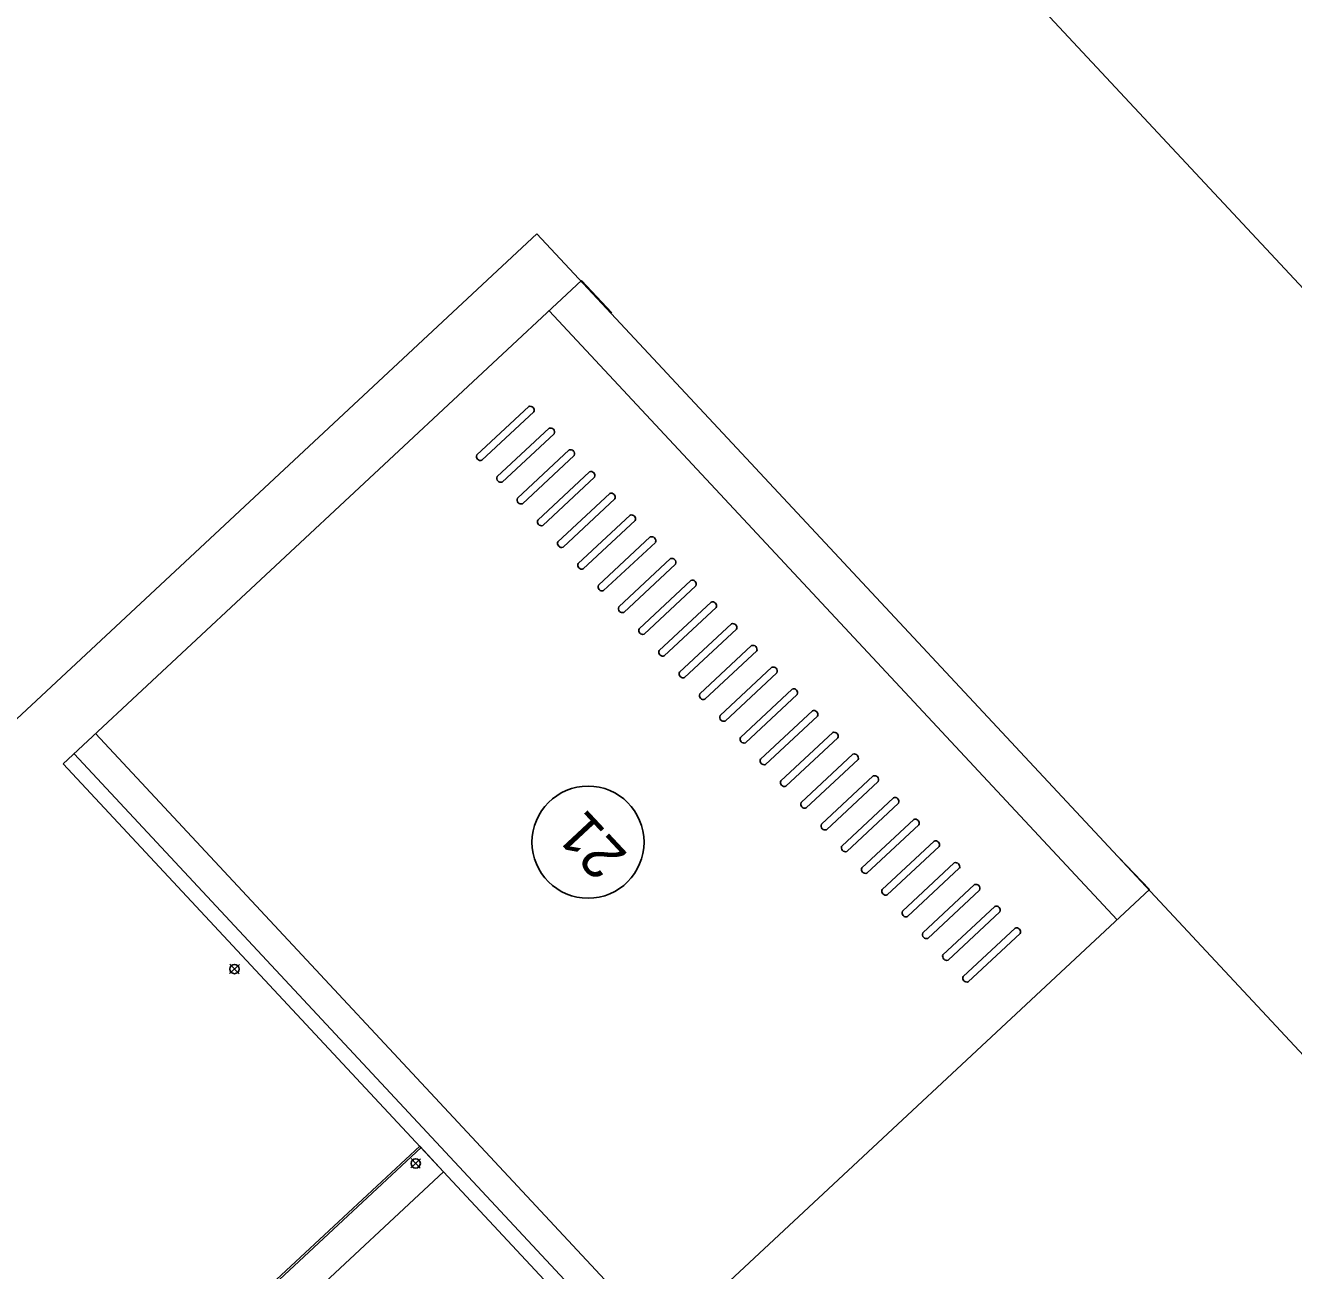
# Model space of a CAD drawing. Extents: x 1121979 to 1130574, y 1838676 to 1848573.
# Drawn here: x 1129637.05 to 1129644.21, y 1839365.55 to 1839372.58 of the extents above; entities that cross this region are included whole.
import ezdxf

# ---------------------------------------------------------------- set-up
doc = ezdxf.new("R2010")
doc.units = 0
for name, color, linetype in [('CENTER1', 7, 'Continuous'), ('IPDC BUILDING RELATED', 7, 'Continuous'), ('IPDC-PROP ELECT EQUIP', 7, 'Continuous'), ('Level 4', 7, 'Continuous'), ('PHANTOM1', 7, 'Continuous')]:
    doc.layers.add(name, color=color, linetype=linetype)

msp = doc.modelspace()

# ---------------------------------------------------------------- linework, layer by layer
at = {"layer": 'CENTER1'}
for points in [[(1129638.2621, 1839367.2816), (1129638.2072, 1839367.2305)], [(1129638.2602, 1839367.2286), (1129638.2091, 1839367.2835)]]:
    msp.add_lwpolyline(points, dxfattribs=at)
at = {"layer": 'IPDC BUILDING RELATED'}
for p, q in [((1129642.1001, 1839373.419), (1129661.457, 1839352.6561)), ((1129639.9419, 1839371.4066), (1129633.3595, 1839365.269)), ((1129639.9419, 1839371.4066), (1129659.302, 1839350.6467))]:
    msp.add_line(p, q, dxfattribs=at)
at = {"layer": 'IPDC-PROP ELECT EQUIP'}
for p, q in [((1129637.2682, 1839368.4147), (1129640.1937, 1839371.1426)), ((1129640.1937, 1839371.1426), (1129640.3642, 1839370.9597)), ((1129643.2161, 1839367.5346), (1129640.0109, 1839370.9721)), ((1129639.8953, 1839370.4311), (1129639.6028, 1839370.1583)), ((1129639.9238, 1839370.4006), (1129639.6312, 1839370.1278)), ((1129640.0097, 1839370.3084), (1129639.7171, 1839370.0356)), ((1129640.0381, 1839370.2779), (1129639.7456, 1839370.0051)), ((1129640.1241, 1839370.1858), (1129639.8315, 1839369.913)), ((1129640.1525, 1839370.1553), (1129639.8599, 1839369.8825)), ((1129640.2384, 1839370.0631), (1129639.9459, 1839369.7903)), ((1129640.2669, 1839370.0326), (1129639.9743, 1839369.7598)), ((1129640.3528, 1839369.9405), (1129640.0602, 1839369.6677)), ((1129640.3812, 1839369.91), (1129640.0887, 1839369.6372)), ((1129640.4672, 1839369.8178), (1129640.1746, 1839369.545)), ((1129640.4956, 1839369.7873), (1129640.203, 1839369.5145)), ((1129640.5815, 1839369.6951), (1129640.289, 1839369.4224)), ((1129640.61, 1839369.6646), (1129640.3174, 1839369.3919)), ((1129640.6959, 1839369.5725), (1129640.4033, 1839369.2997)), ((1129640.7243, 1839369.542), (1129640.4318, 1839369.2692)), ((1129640.8103, 1839369.4498), (1129640.5177, 1839369.1771)), ((1129640.8387, 1839369.4193), (1129640.5461, 1839369.1466)), ((1129640.9246, 1839369.3272), (1129640.6321, 1839369.0544)), ((1129640.9531, 1839369.2967), (1129640.6605, 1839369.0239)), ((1129641.039, 1839369.2045), (1129640.7464, 1839368.9317)), ((1129641.0674, 1839369.174), (1129640.7749, 1839368.9013)), ((1129641.1534, 1839369.0819), (1129640.8608, 1839368.8091)), ((1129641.1818, 1839369.0514), (1129640.8892, 1839368.7786)), ((1129641.2677, 1839368.9592), (1129640.9752, 1839368.6864)), ((1129641.2962, 1839368.9287), (1129641.0036, 1839368.6559)), ((1129641.3821, 1839368.8366), (1129641.0895, 1839368.5638)), ((1129641.4105, 1839368.8061), (1129641.118, 1839368.5333)), ((1129641.4964, 1839368.7139), (1129641.2039, 1839368.4411)), ((1129641.5249, 1839368.6834), (1129641.2323, 1839368.4106)), ((1129641.6108, 1839368.5913), (1129641.3183, 1839368.3185)), ((1129640.6563, 1839365.1477), (1129637.451, 1839368.5852)), ((1129641.6392, 1839368.5608), (1129641.3467, 1839368.288)), ((1129640.5343, 1839365.034), (1129637.3291, 1839368.4715)), ((1129641.7252, 1839368.4686), (1129641.4326, 1839368.1958)), ((1129640.4734, 1839364.9772), (1129637.2682, 1839368.4147)), ((1129641.7536, 1839368.4381), (1129641.4611, 1839368.1653)), ((1129641.8395, 1839368.346), (1129641.547, 1839368.0732)), ((1129641.868, 1839368.3155), (1129641.5754, 1839368.0427)), ((1129641.9539, 1839368.2233), (1129641.6614, 1839367.9505)), ((1129641.9823, 1839368.1928), (1129641.6898, 1839367.92)), ((1129642.0683, 1839368.1007), (1129641.7757, 1839367.8279)), ((1129642.0967, 1839368.0702), (1129641.8042, 1839367.7974)), ((1129642.1826, 1839367.978), (1129641.8901, 1839367.7052)), ((1129642.2111, 1839367.9475), (1129641.9185, 1839367.6747)), ((1129643.399, 1839367.705), (1129643.2258, 1839367.8853)), ((1129642.297, 1839367.8553), (1129642.0044, 1839367.5826)), ((1129642.3254, 1839367.8248), (1129642.0329, 1839367.5521)), ((1129642.4114, 1839367.7327), (1129642.1188, 1839367.4599)), ((1129640.4734, 1839364.9772), (1129643.399, 1839367.705)), ((1129642.4398, 1839367.7022), (1129642.1472, 1839367.4294)), ((1129642.5257, 1839367.61), (1129642.2332, 1839367.3373)), ((1129642.5542, 1839367.5795), (1129642.2616, 1839367.3068)), ((1129642.6401, 1839367.4874), (1129642.3475, 1839367.2146)), ((1129642.6685, 1839367.4569), (1129642.376, 1839367.1841))]:
    msp.add_line(p, q, dxfattribs=at)
msp.add_lwpolyline([(1129639.4152, 1839366.1121), (1129639.28, 1839366.2571), (1129638.4724, 1839365.5041), (1129638.6077, 1839365.3591)], close=True, dxfattribs=at)
for points in [[(1129638.4882, 1839365.5036), (1129639.2876, 1839366.249)], [(1129639.285, 1839366.1845), (1129639.2301, 1839366.1334)], [(1129639.232, 1839366.1864), (1129639.2831, 1839366.1315)]]:
    msp.add_lwpolyline(points, dxfattribs=at)
msp.add_circle((1129639.2576, 1839366.159), 0.026, dxfattribs=at)
for centre, start, end in [((1129639.9032, 1839370.4099), 335.51952, 110.47477), ((1129640.0176, 1839370.2873), 335.51952, 110.47477), ((1129640.132, 1839370.1646), 335.51952, 110.47477), ((1129639.6233, 1839370.1489), 155.51952, 290.47477), ((1129639.7377, 1839370.0263), 155.51952, 290.47477), ((1129640.2463, 1839370.042), 335.51952, 110.47477), ((1129639.8521, 1839369.9036), 155.51952, 290.47477), ((1129640.3607, 1839369.9193), 335.51952, 110.47477), ((1129640.4751, 1839369.7967), 335.51952, 110.47477), ((1129639.9664, 1839369.781), 155.51952, 290.47477), ((1129640.0808, 1839369.6583), 155.51952, 290.47477), ((1129640.5894, 1839369.674), 335.51952, 110.47477), ((1129640.1951, 1839369.5357), 155.51952, 290.47477), ((1129640.7038, 1839369.5513), 335.51952, 110.47477), ((1129640.8182, 1839369.4287), 335.51952, 110.47477), ((1129640.3095, 1839369.413), 155.51952, 290.47477), ((1129640.9325, 1839369.306), 335.51952, 110.47477), ((1129640.4239, 1839369.2904), 155.51952, 290.47477), ((1129640.5382, 1839369.1677), 155.51952, 290.47477), ((1129641.0469, 1839369.1834), 335.51952, 110.47477), ((1129640.6526, 1839369.045), 155.51952, 290.47477), ((1129641.1612, 1839369.0607), 335.51952, 110.47477), ((1129641.2756, 1839368.9381), 335.51952, 110.47477), ((1129640.767, 1839368.9224), 155.51952, 290.47477), ((1129640.8813, 1839368.7997), 155.51952, 290.47477), ((1129641.39, 1839368.8154), 335.51952, 110.47477), ((1129640.9957, 1839368.6771), 155.51952, 290.47477), ((1129641.5043, 1839368.6928), 335.51952, 110.47477), ((1129641.6187, 1839368.5701), 335.51952, 110.47477), ((1129641.1101, 1839368.5544), 155.51952, 290.47477), ((1129641.7331, 1839368.4475), 335.51952, 110.47477), ((1129641.2244, 1839368.4318), 155.51952, 290.47477), ((1129641.3388, 1839368.3091), 155.51952, 290.47477), ((1129641.8474, 1839368.3248), 335.51952, 110.47477), ((1129641.4532, 1839368.1865), 155.51952, 290.47477), ((1129641.9618, 1839368.2022), 335.51952, 110.47477), ((1129642.0762, 1839368.0795), 335.51952, 110.47477), ((1129641.5675, 1839368.0638), 155.51952, 290.47477), ((1129641.6819, 1839367.9412), 155.51952, 290.47477), ((1129642.1905, 1839367.9569), 335.51952, 110.47477), ((1129641.7963, 1839367.8185), 155.51952, 290.47477), ((1129642.3049, 1839367.8342), 335.51952, 110.47477), ((1129642.4193, 1839367.7115), 335.51952, 110.47477), ((1129641.9106, 1839367.6959), 155.51952, 290.47477), ((1129642.5336, 1839367.5889), 335.51952, 110.47477), ((1129642.025, 1839367.5732), 155.51952, 290.47477), ((1129642.1394, 1839367.4506), 155.51952, 290.47477), ((1129642.648, 1839367.4662), 335.51952, 110.47477), ((1129642.2537, 1839367.3279), 155.51952, 290.47477), ((1129642.3681, 1839367.2052), 155.51952, 290.47477)]:
    msp.add_arc(centre, 0.0226, start, end, dxfattribs=at)
at = {"layer": 'Level 4'}
msp.add_circle((1129640.2299, 1839367.9723), 0.3163, dxfattribs=at)
at = {"layer": 'PHANTOM1'}
msp.add_circle((1129638.2346, 1839367.256), 0.026, dxfattribs=at)

# ---------------------------------------------------------------- texts
at = {"layer": 'Level 4'}
msp.add_text('21', height=0.24, rotation=132.99715, dxfattribs=at).set_placement((1129640.4595, 1839367.902))

doc.saveas('drawing.dxf')
